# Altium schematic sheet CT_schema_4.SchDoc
size 298 x 247 mm
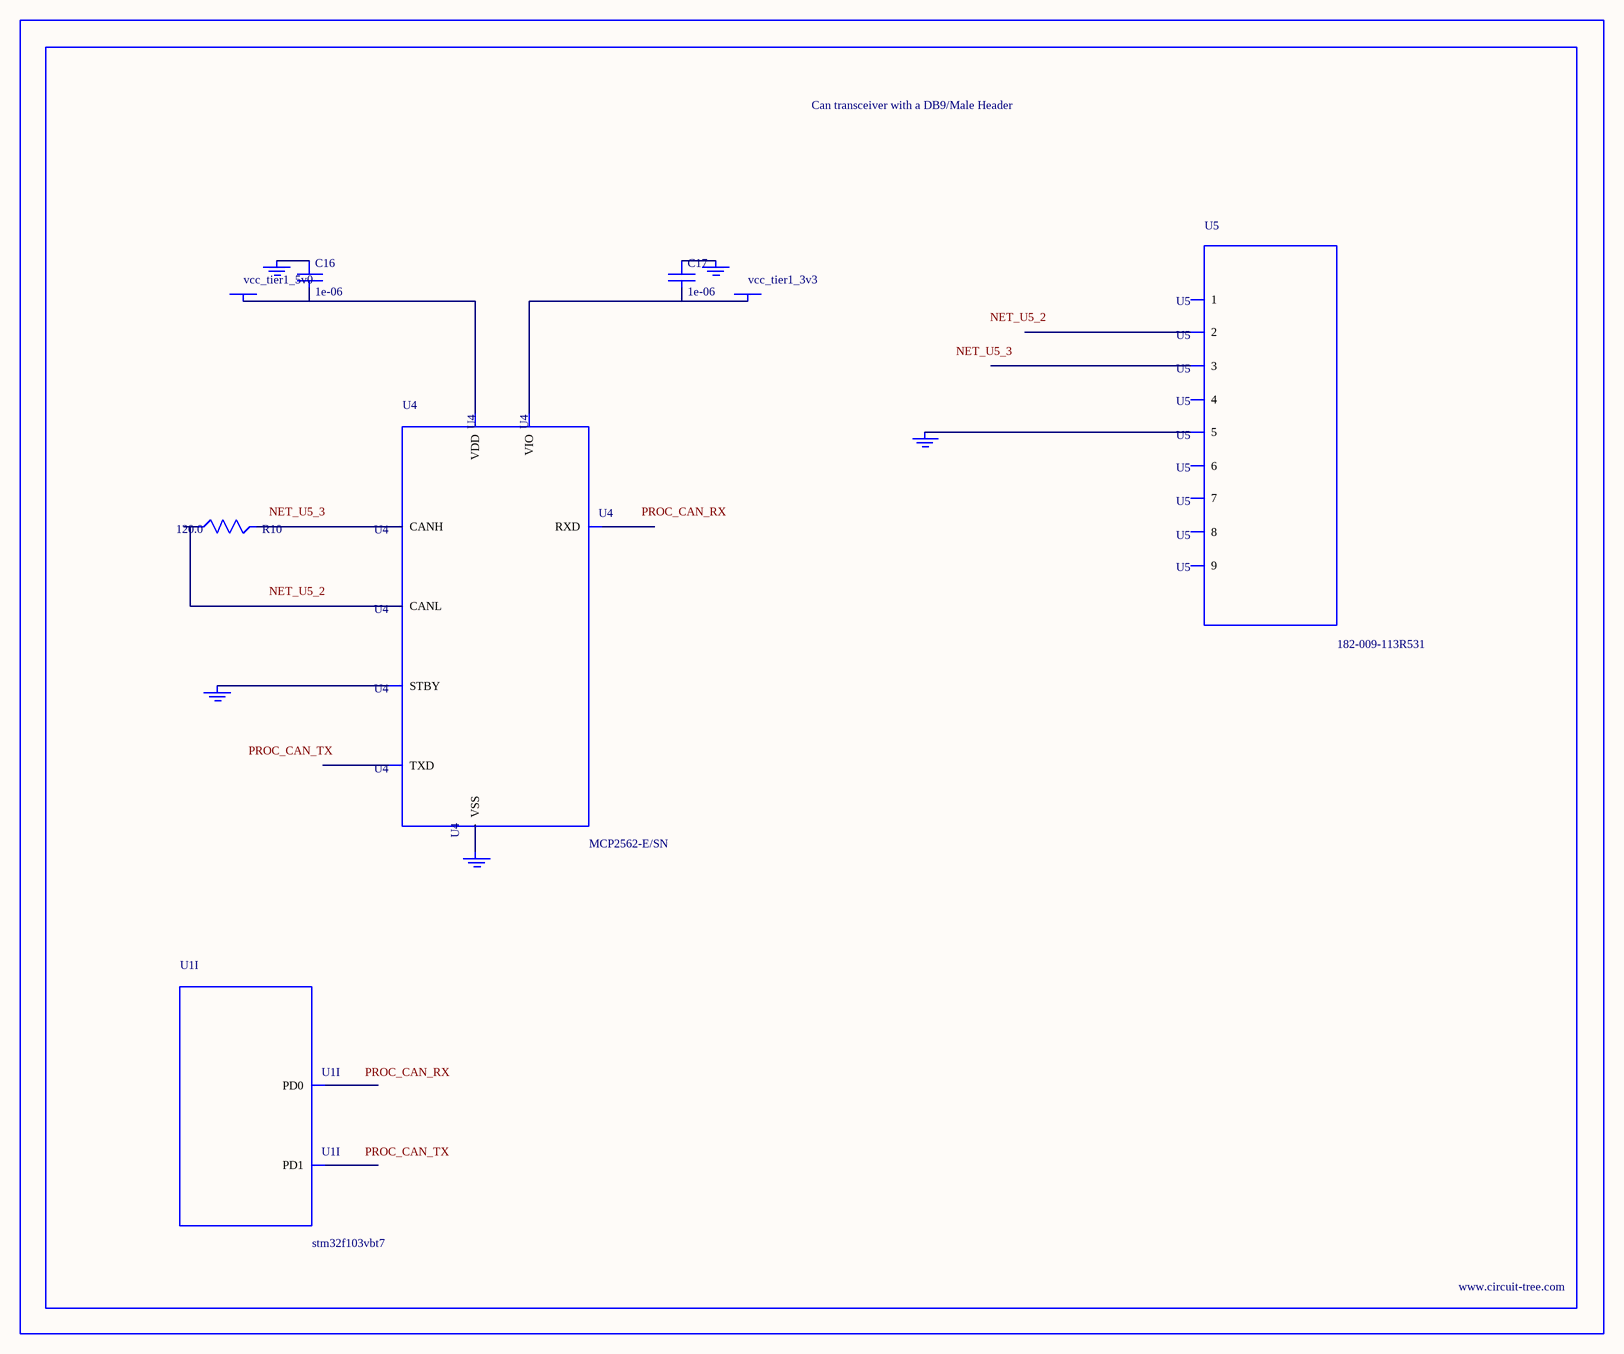
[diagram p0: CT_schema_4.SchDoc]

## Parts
BORDER3  (no value)
C16  1e-06  [C0603]
C17  1e-06  [C0603]
GND_INSTANCE_3_0  (no value)
GND_INSTANCE_3_1  (no value)
GND_INSTANCE_3_2  (no value)
GND_INSTANCE_3_3  (no value)
GND_INSTANCE_3_4  (no value)
POWER_INSTANCE_3_0  vcc_tier1_5v0
POWER_INSTANCE_3_1  vcc_tier1_3v3
R10  120.0  [R0603]
U1  stm32f103vbt7  [LQFP100]  (part I of 11)
U4  MCP2562-E/SN  [SOIC-8]
U5  182-009-113R531  [182-009-MALE]

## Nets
NetC16_1: C16.1 GND_INSTANCE_3_0.0(GND)
NetC16_2: C16.2 POWER_INSTANCE_3_0.0(PWR) U4.3(VDD)
NetC17_1: C17.1 GND_INSTANCE_3_1.0(GND)
NetC17_2: C17.2 POWER_INSTANCE_3_1.0(PWR) U4.5(VIO)
NetGND_INSTANCE_3_2_0: GND_INSTANCE_3_2.0(GND) U4.8(STBY)
NetGND_INSTANCE_3_3_0: GND_INSTANCE_3_3.0(GND) U4.2(VSS)
NetGND_INSTANCE_3_4_0: GND_INSTANCE_3_4.0(GND) U5.5
NetR10_1: R10.1 U4.6(CANL)
NetR10_2: R10.2 U4.7(CANH)

Not connected (* = marked no-connect by the designer): U1 81(PD0) 82(PD1); U4 1(TXD) 4(RXD); U5 1 2 3 4 6 7 8 9

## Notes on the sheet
- Labels drawn without touching a wire or pin: NET_U5_2, NET_U5_3, PROC_CAN_RX, PROC_CAN_TX

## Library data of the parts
BORDER3 = BORDER_PAGE3
C16 C17 = C0603C105K3RACTU
GND_INSTANCE_3_0-GND_INSTANCE_3_4 = GND
POWER_INSTANCE_3_0 POWER_INSTANCE_3_1 = PWR
R10 = RC0603JR-07120RL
